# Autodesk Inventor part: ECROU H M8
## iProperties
Created: 2004-11
Part Number: ECROU H M8
Document SubType Name: Modeling
Designer: Bruno
Manufacturer: Standard
Standards Organization: Custom
Author: Bruno
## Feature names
1. Base1
